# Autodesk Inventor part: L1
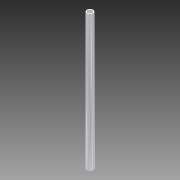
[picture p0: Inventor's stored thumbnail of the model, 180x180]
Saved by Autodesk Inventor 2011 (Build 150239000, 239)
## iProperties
Created: 2014-02
Part Number: L1
Document SubType Name: Modeling
Designer: Evgeny
Density: 1 g/cm^3
Author: Evgeny
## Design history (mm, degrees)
sketch "Эскиз1"
  geometry: C1 r 4 at (0, 0); 1 further point
  constraints: 1 centre point, 1 coincident
  dimensions: "d0" = 8 diameter of C1
extrude "Выдавливание1" new body sketch "Эскиз1" distance "d1" = 177; taper "d2" = 0 deg
feature "Оболочка1" dims "d3" = 1
node "Твердое тело1"
